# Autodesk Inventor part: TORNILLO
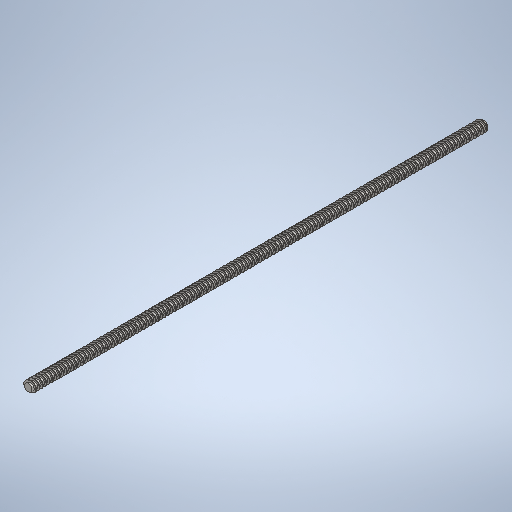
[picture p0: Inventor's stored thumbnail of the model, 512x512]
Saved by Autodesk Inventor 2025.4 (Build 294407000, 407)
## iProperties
Created: 2026-04
Part Number: TORNILLO
Material: Steel, Alloy
Document SubType Name: Modeling
Designer: PC
Density: 7.73 g/cm^3
Appearance: Stainless - Brushed
Author: PC
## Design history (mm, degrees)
sketch "Sketch1"
  geometry: C1 r 3.25 at (0, 0); 1 further point
  constraints: 1 centre point, 1 coincident
  dimensions: "d0" = 6.5 diameter of C1
extrude "Extrusion1" new body sketch "Sketch1" distance "d1" = 400; taper "d2" = 0 deg
sketch "Sketch2"
  geometry: L1 (3.25, 0)-(-3.25, 0) reference; L2 (3.25, 0)-(4.75, 0); L3 (4.75, 0)-(4.75, 0.5); L4 (5.329, 0.5)-(3.25, 0.5); L5 (3.25, 0)-(3.25, 400) reference; L6 (3.25, 0)-(3.25, 0.5); L7 (0, 0)-(0, 400); L8 (3.25, 0.5)-(4.75, 0.5); L9 (4.75, 0.5)-(4.75, 0); L10 (4.75, 0)-(3.25, 0); L11 (3.25, 0)-(3.25, 0.5)
  constraints: 18 end point, 3 horizontal, 2 parallel, 2 perpendicular, 1 collinear, 1 point on line, 1 vertical
  dimensions: "d3" = 1.5 distance of L1.start L2.end; "d4" = 0.5 distance of L2.end L3.end; "d5" = 400 distance of L7.start L7.end
sketch "Sketch3"
  geometry: L1 (0, 0)-(0, 0)
  constraints: 2 end point, 1 vertical
coil "Coil1" pitch "d7" = 3; turns "d9" = 133; dims "d8" = 10, "d10" = 0, angle "d11" = 90 deg, angle "d12" = 90 deg, "d13" = 0, "d14" = 0
body "Solid1"
